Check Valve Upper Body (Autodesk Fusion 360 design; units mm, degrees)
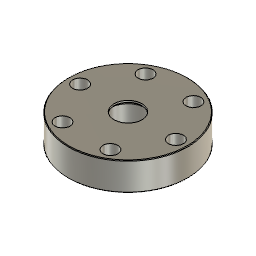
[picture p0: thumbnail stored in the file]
description: Part Number
part number: 9559K114_Ultra-Chemical-Resistant Rigid PTFE O-Ring
sketch "Sketch1" plane through (0, 0, 0) normal (0, 1, 0) x axis (1, 0, 0)
  line L1 (5.1816, -6.5786) -> (5.1816, 0)
  line L2 (30.734, -8.2042) -> (4.064, -8.2042)
  line L3 (17.399, -8.2042) -> (17.399, 0)
  line L4 (17.399, -8.2042) -> (4.064, -8.2042)
  line L5 (5.1816, -6.5786) -> (4.064, -7.6962)
  line L6 (4.064, -7.6962) -> (4.064, -8.2042)
  line L7 (17.399, 0) -> (5.1816, 0)
  line L8 (0, 6.4615) -> (0, -18.5264)
  line L9 (10.3632, 0) -> (0, 0)
  line L10 (10.3632, -1.0668) -> (10.3632, 0)
  line L11 (7.7978, -1.0668) -> (10.3632, -1.0668)
  line L12 (7.7978, 0.0002) -> (7.7978, -1.0668)
  line L13 (5.969, -6.5786) -> (5.1816, -6.5786)
  line L14 (5.969, 0) -> (5.969, -6.5786)
  line L15 (5.1816, 0) -> (5.969, 0)
  point P7 (17.399, -8.2042)
  point P1 (0, 0)
  point P3 (5.1816, -6.5786)
  point P8 (5.1816, -6.5786)
  point P12 (0, 0)
  point P18 (5.969, 0)
  point P4 (4.064, -8.2042)
  point P9 (4.064, -7.6962)
  point P13 (10.3632, 0)
  point P14 (10.3632, -1.0668)
  point P15 (7.7978, -1.0668)
  midpoint L2 P7
  coincident P1 L7
  vertical L8
  coincident P1 L8
  vertical L3
  horizontal L7
  vertical L1
  vertical L6
  coincident P3 P8
  coincident P1 P12
  perpendicular L1 L9
  perpendicular L7 L10
  perpendicular L10 L11
  perpendicular L1 L13
  coincident L9 P18
  perpendicular L9 L14
  dimension "d55" = 10.3632
  dimension "d56" = 34.798
  dimension "d57" distance L4 L7 = 8.2042
  dimension "d58" angle L4 L5 = 45
  dimension "d59" distance P4 P9 = 0.508
  dimension "d60" = 8.128
  dimension "d65" distance P12 P13 = 10.3632
  dimension "d66" distance P13 P14 = 1.0668
  dimension "d67" distance P14 P15 = 2.5654
  dimension "d68" angle L11 L12 = 90
  dimension "d74" = 11.938
revolve "Revolve1" sketch "Sketch1" AlongAngle 360
sketch "Sketch4" plane through (0, 0, 8.2042) normal (0, 0, 1) x axis (-1, 0, 0)
  line L1 (13.97, 0) -> (0, 0)
  circle C1 centre (0, 0) radius 17.399
  circle C2 centre (0, 0) radius 4.064
  point P2 (0, 0)
  point P3 (0, 0)
  point P4 (13.97, 0)
  coincident P2 P3
  horizontal L1
  dimension "d13" distance P3 P4 = 13.97
hole "Hole1" HoleDiameter 4.318 TipAngle 118
circular_pattern "C-Pattern1" TotalAngle 360
base_feature "Base Feature"
delete_face "DeleteFace1"
revolve "Revolve5" sketch "Sketch1" AlongAngle 360
revolve "Revolve6" sketch "Sketch1" AlongAngle 360
chamfer "Chamfer1" distance 0.1778 distance 0.1778
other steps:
create_component "CreateComponent6"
